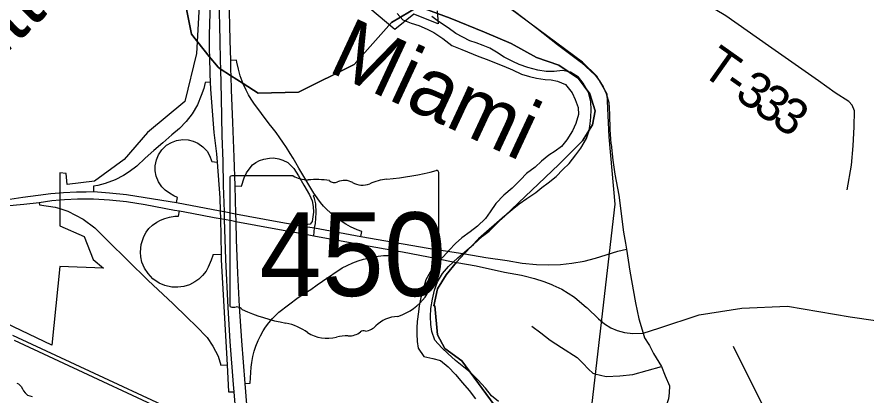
# Model space of a CAD drawing. Extents: x 44.2 to 78.2, y 4.5 to 26.5.
# Drawn here: x 50.4 to 51.74, y 20.558 to 21.155 of the extents above; entities that cross this region are included whole.
import ezdxf

# ---------------------------------------------------------------- set-up
doc = ezdxf.new("R2010")
doc.units = 0
for name, color, linetype in [('GM_X_Corporation', 7, 'Continuous'), ('GM_X_County_Road', 7, 'Continuous'), ('GM_X_Interchange_Ramps', 7, 'Continuous'), ('GM_X_Interstate_Route', 7, 'Continuous'), ('GM_X_Major_River', 7, 'Continuous'), ('GM_X_Major_River_Text', 7, 'Continuous'), ('GM_X_Minor_River', 7, 'Continuous'), ('GM_X_Rail_Line', 7, 'Continuous'), ('GM_X_State_Location', 7, 'Continuous'), ('GM_X_State_Route', 7, 'Continuous'), ('GM_X_State_Shield', 7, 'Continuous'), ('GM_X_Township_Road', 7, 'Continuous'), ('GM_X_Township_Road_Text', 7, 'Continuous'), ('GM_X_US_Route', 7, 'Continuous')]:
    doc.layers.add(name, color=color, linetype=linetype)

msp = doc.modelspace()

# ---------------------------------------------------------------- linework, layer by layer
at = {"layer": 'GM_X_Corporation'}
for points in [[(51.0623, 21.1648), (51.0641, 21.1438), (51.0258, 21.1593), (50.996, 21.1352), (50.8511, 21.2568)], [(50.6902, 21.2298), (50.6832, 21.0974), (50.6644, 21.0219), (50.6057, 20.9726), (50.5688, 20.9301), (50.5222, 20.8962), (50.4792, 20.891), (50.4777, 20.9083), (50.4673, 20.9092), (50.4673, 20.8259), (50.5059, 20.8087), (50.5198, 20.7725), (50.5363, 20.7591), (50.4673, 20.7615), (50.455, 20.6374), (50.3201, 20.7016)]]:
    msp.add_lwpolyline(points, dxfattribs=at)
at = {"layer": 'GM_X_County_Road'}
msp.add_lwpolyline([(50.3952, 20.6454), (50.7135, 20.4974)], dxfattribs=at)
at = {"layer": 'GM_X_Interchange_Ramps'}
for points in [[(50.7166, 21.2485), (50.7105, 21.2484), (50.7063, 21.2085), (50.7042, 21.1601), (50.7031, 21.1275), (50.7031, 21.1023), (50.7034, 21.0922), (50.7042, 21.0655), (50.7048, 21.0521)], [(50.7568, 21.0494), (50.755, 21.0538), (50.7521, 21.0623), (50.7491, 21.0728), (50.7464, 21.0837), (50.7459, 21.0866), (50.7364, 21.0864)], [(50.7048, 21.0521), (50.6967, 21.0518), (50.6943, 21.0422), (50.6906, 21.0309), (50.6848, 21.0165), (50.6762, 21.0022), (50.6666, 20.9902), (50.656, 20.9792), (50.644, 20.9689), (50.6299, 20.9566), (50.6156, 20.9446), (50.6022, 20.9323), (50.5888, 20.9199), (50.5768, 20.911), (50.5679, 20.9052), (50.5546, 20.8984), (50.5391, 20.8922), (50.5275, 20.8894), (50.5203, 20.8884), (50.5203, 20.8796)], [(50.7048, 21.0521), (50.7052, 21.0413), (50.7105, 20.973), (50.7147, 20.9394), (50.7157, 20.9263)], [(50.9422, 20.8088), (50.9435, 20.8168), (50.9364, 20.8193), (50.9261, 20.8243), (50.9184, 20.8284), (50.9111, 20.833), (50.9053, 20.8371), (50.8997, 20.8414), (50.8936, 20.8466), (50.8886, 20.8514), (50.8834, 20.8568), (50.8785, 20.8626), (50.8742, 20.8681), (50.8695, 20.875), (50.8682, 20.877), (50.8446, 20.9164), (50.8398, 20.9249), (50.8355, 20.9322), (50.8309, 20.9398), (50.825, 20.9489), (50.8191, 20.9577), (50.8146, 20.9643), (50.8085, 20.9727), (50.8023, 20.9809), (50.7978, 20.9867), (50.7736, 21.019), (50.7694, 21.0251), (50.765, 21.0324), (50.7612, 21.0396), (50.7568, 21.0494)], [(50.6515, 20.8623), (50.653, 20.8702), (50.6472, 20.8729), (50.6403, 20.8773), (50.6338, 20.882), (50.6284, 20.8873), (50.6233, 20.8949), (50.6196, 20.9039), (50.618, 20.9125), (50.618, 20.9205), (50.6199, 20.9299), (50.6232, 20.9378), (50.6284, 20.9455), (50.6359, 20.9526), (50.6435, 20.9572), (50.6514, 20.9601), (50.6613, 20.9617), (50.6697, 20.9612), (50.6775, 20.9594), (50.6851, 20.956), (50.6931, 20.9504), (50.6996, 20.9433), (50.7041, 20.9357), (50.7069, 20.9279), (50.7071, 20.9269), (50.7157, 20.9263)], [(50.7157, 20.9263), (50.72, 20.87), (50.7204, 20.8491), (50.7207, 20.8372), (50.7219, 20.7803)], [(50.7434, 20.8885), (50.7539, 20.8881), (50.758, 20.9015), (50.7619, 20.9093), (50.7675, 20.9173), (50.7714, 20.9217), (50.7766, 20.9256), (50.7823, 20.9286), (50.7894, 20.9308), (50.7983, 20.9325), (50.8042, 20.9329), (50.8126, 20.9312), (50.8189, 20.9292), (50.8269, 20.9256), (50.8317, 20.921), (50.8365, 20.9162), (50.8439, 20.9043), (50.8523, 20.89), (50.8614, 20.8748), (50.8655, 20.8651), (50.8668, 20.8562), (50.8673, 20.8471), (50.8666, 20.8399), (50.8655, 20.8328), (50.8621, 20.8284), (50.8548, 20.8271), (50.8545, 20.8249)], [(50.8679, 20.8102), (50.8693, 20.8223), (50.8705, 20.8294), (50.8718, 20.8463), (50.8713, 20.8603), (50.8691, 20.8687), (50.8675, 20.873), (50.8695, 20.875)], [(50.4348, 20.8627), (50.4355, 20.8589), (50.4602, 20.8549), (50.4673, 20.8528)], [(50.4673, 20.8528), (50.4803, 20.8489), (50.504, 20.8363), (50.5224, 20.8226), (50.5431, 20.8022), (50.5753, 20.7704), (50.6061, 20.7401), (50.6463, 20.7026), (50.6682, 20.6814), (50.6825, 20.6676), (50.6999, 20.6495), (50.7089, 20.6363), (50.7172, 20.6201), (50.7216, 20.606), (50.7313, 20.6065)], [(50.7219, 20.7803), (50.7087, 20.7799), (50.7085, 20.7789), (50.7062, 20.7716), (50.7015, 20.7604), (50.698, 20.7542), (50.6926, 20.7473), (50.6867, 20.7416), (50.6806, 20.7373), (50.6718, 20.7328), (50.663, 20.7301), (50.6537, 20.7288), (50.6441, 20.7292), (50.6333, 20.7316), (50.6242, 20.7355), (50.6142, 20.7423), (50.6065, 20.7504), (50.6009, 20.759), (50.597, 20.7684), (50.5951, 20.7767), (50.5945, 20.7844), (50.5956, 20.7963), (50.5997, 20.8088), (50.6034, 20.8155), (50.608, 20.8217), (50.6138, 20.827), (50.6203, 20.8316), (50.6262, 20.8348), (50.6329, 20.8375), (50.6402, 20.8395), (50.649, 20.8408), (50.6546, 20.8409), (50.6561, 20.8493)], [(50.7219, 20.7803), (50.7221, 20.7722), (50.7313, 20.6065), (50.7336, 20.564), (50.7418, 20.5642)], [(50.7593, 20.577), (50.7677, 20.5775), (50.7692, 20.6031), (50.77, 20.6102), (50.7717, 20.6198), (50.7738, 20.6282), (50.7764, 20.6361), (50.78, 20.645), (50.7837, 20.6526), (50.7881, 20.6603), (50.7918, 20.666), (50.797, 20.673), (50.8026, 20.6795), (50.8084, 20.6855), (50.8126, 20.6894), (50.8431, 20.7127), (50.8541, 20.7197), (50.8631, 20.7256), (50.8731, 20.7325), (50.8817, 20.7386), (50.9129, 20.7594), (50.9206, 20.7633), (50.9296, 20.7672), (50.9381, 20.7704), (50.9464, 20.773), (50.9536, 20.7749), (50.9609, 20.7764), (50.9696, 20.7779), (50.978, 20.7788), (50.9848, 20.7792), (50.9919, 20.7793), (50.9974, 20.7789), (50.9986, 20.7863)]]:
    msp.add_lwpolyline(points, dxfattribs=at)
at = {"layer": 'GM_X_Interstate_Route'}
for points in [[(50.7181, 21.1857), (50.7198, 21.1179), (50.7205, 21.0861), (50.7207, 21.0727), (50.7218, 21.0275), (50.7232, 20.9673), (50.7243, 20.9274), (50.7253, 20.8894), (50.7264, 20.8481), (50.7267, 20.8361), (50.7288, 20.7728), (50.7323, 20.6971), (50.7358, 20.6432), (50.7407, 20.5758), (50.7418, 20.5642), (50.7453, 20.5188)], [(50.7341, 21.186), (50.7357, 21.1182), (50.7364, 21.0864)], [(50.7364, 21.0864), (50.7368, 21.0715), (50.737, 21.0622), (50.7375, 21.0398), (50.7399, 20.9886), (50.742, 20.9341), (50.7434, 20.8885), (50.7445, 20.8446), (50.7448, 20.8328), (50.7456, 20.8038), (50.7478, 20.7513), (50.7503, 20.6987), (50.7539, 20.6447), (50.7593, 20.577), (50.7644, 20.5113)]]:
    msp.add_lwpolyline(points, dxfattribs=at)
at = {"layer": 'GM_X_Major_River'}
for points in [[(50.9993, 21.1602), (51.0082, 21.1505), (51.0218, 21.1453), (51.0335, 21.1413), (51.047, 21.1357), (51.0572, 21.1305), (51.0714, 21.1207), (51.0856, 21.1098), (51.1014, 21.1037), (51.1285, 21.0925), (51.1413, 21.0881), (51.1529, 21.0833), (51.1676, 21.0773), (51.1811, 21.0713), (51.1954, 21.0649), (51.2079, 21.0608), (51.2192, 21.0583), (51.2328, 21.0565), (51.2423, 21.0556), (51.2521, 21.0535), (51.2649, 21.0486), (51.2756, 21.0351), (51.28, 21.0248), (51.285, 21.0121), (51.2855, 21.0011), (51.2814, 20.9871), (51.2762, 20.9754), (51.2672, 20.9611), (51.2586, 20.9506), (51.2489, 20.9432), (51.2389, 20.937), (51.2273, 20.9277), (51.2169, 20.9184), (51.2034, 20.908), (51.194, 20.898), (51.1809, 20.8849), (51.1677, 20.8738), (51.1549, 20.8607), (51.1463, 20.848), (51.1388, 20.8375), (51.1264, 20.8252), (51.1148, 20.8163), (51.1017, 20.8067), (51.0916, 20.7981), (51.0815, 20.7873), (51.0726, 20.7776), (51.0621, 20.7679), (51.0515, 20.7526), (51.0448, 20.7405), (51.0407, 20.7254), (51.037, 20.7126), (51.0344, 20.6997), (51.0331, 20.6902), (51.0312, 20.675), (51.0303, 20.6648), (51.0304, 20.6553), (51.0309, 20.6435), (51.0326, 20.6331), (51.0414, 20.6197), (51.0558, 20.6167), (51.0679, 20.6134), (51.0798, 20.6033), (51.0913, 20.5916), (51.1024, 20.5785), (51.1131, 20.5661), (51.1231, 20.5533)], [(51.2857, 21.06), (51.2729, 21.0679), (51.2601, 21.0704), (51.2471, 21.0688), (51.2346, 21.069), (51.2214, 21.0708), (51.2055, 21.075), (51.192, 21.0798), (51.1818, 21.0846), (51.1683, 21.0917), (51.1559, 21.0992), (51.1454, 21.1055), (51.1349, 21.1099), (51.124, 21.1139), (51.1142, 21.1172), (51.1029, 21.1231), (51.092, 21.1287), (51.0797, 21.1377), (51.0644, 21.1479), (51.0543, 21.1557)], [(51.1595, 20.5491), (51.1483, 20.5577), (51.139, 20.5697), (51.1268, 20.5829), (51.1145, 20.5949), (51.1048, 20.6031), (51.0914, 20.6133), (51.0795, 20.6246), (51.0698, 20.6335), (51.0591, 20.6455), (51.0541, 20.6593), (51.0528, 20.67), (51.0519, 20.683), (51.0526, 20.6955), (51.0552, 20.7103), (51.0581, 20.7243), (51.063, 20.7375), (51.0712, 20.7506), (51.0806, 20.7615), (51.0949, 20.7753), (51.1061, 20.7845), (51.1201, 20.7964), (51.134, 20.8094), (51.1444, 20.8172), (51.1573, 20.8299), (51.1681, 20.8411), (51.1809, 20.8515), (51.1917, 20.8604), (51.204, 20.8689), (51.2179, 20.8785), (51.2276, 20.8859), (51.2376, 20.8933), (51.2504, 20.9037), (51.2608, 20.9145), (51.2705, 20.9238), (51.2811, 20.9376), (51.2889, 20.9481), (51.298, 20.9631), (51.302, 20.976), (51.3038, 20.9862), (51.3048, 20.9969), (51.3054, 21.0086), (51.3049, 21.0212), (51.3011, 21.0361), (51.2927, 21.0504), (51.2857, 21.06)]]:
    msp.add_lwpolyline(points, dxfattribs=at)
at = {"layer": 'GM_X_Minor_River'}
msp.add_lwpolyline([(50.3997, 20.578), (50.4023, 20.5768), (50.4064, 20.5725), (50.4086, 20.5686), (50.4104, 20.5656), (50.4126, 20.5625), (50.4167, 20.5589), (50.4201, 20.5577), (50.4238, 20.5569)], dxfattribs=at)
at = {"layer": 'GM_X_Rail_Line'}
for points in [[(51.7576, 19.9172), (51.6529, 19.9117), (51.5311, 19.911), (51.4655, 19.9391), (51.4402, 19.9542), (51.2895, 20.2613), (51.2813, 20.3233), (51.3434, 20.8596), (51.3339, 20.9662), (51.3307, 21.0331), (51.3143, 21.0616), (51.2918, 21.0838), (51.0931, 21.2312)], [(50.6639, 21.1832), (50.675, 21.1279), (50.7032, 21.0927), (50.7169, 21.0756), (50.7205, 21.0733), (50.7368, 21.0627), (50.7566, 21.0499), (50.7803, 21.0346), (50.844, 21.0365), (50.9317, 21.0802), (50.9905, 21.1461), (51.0331, 21.1714), (51.0833, 21.153), (51.1374, 21.1309), (51.1794, 21.1133), (51.2191, 21.0912), (51.2545, 21.079), (51.2854, 21.058), (51.3031, 21.0337), (51.3119, 21.0072), (51.3075, 20.9851), (51.292, 20.9597), (51.2545, 20.9222), (51.1694, 20.8415), (51.1275, 20.8051), (51.1057, 20.782), (51.0931, 20.7685), (51.0766, 20.7487), (51.0631, 20.7264), (51.0575, 20.6994), (51.0589, 20.6994), (51.0631, 20.6539), (51.0745, 20.6326), (51.1015, 20.6127), (51.2106, 20.4645)], [(51.2106, 20.4645), (51.1015, 20.6127), (51.0745, 20.6326), (51.0631, 20.6539), (51.0589, 20.6994), (51.0575, 20.6994), (51.0631, 20.7264), (51.0766, 20.7487), (51.0931, 20.7685), (51.1057, 20.782), (51.1275, 20.8051), (51.1694, 20.8415), (51.2545, 20.9222), (51.292, 20.9597), (51.3075, 20.9851), (51.3119, 21.0072), (51.3031, 21.0337), (51.2854, 21.058), (51.2545, 21.079), (51.2191, 21.0912), (51.1794, 21.1133), (51.1374, 21.1309), (51.0833, 21.153), (51.0331, 21.1714), (50.9905, 21.1461), (50.9317, 21.0802), (50.844, 21.0365), (50.7803, 21.0346), (50.7566, 21.0499), (50.7368, 21.0627), (50.7205, 21.0733), (50.7169, 21.0756), (50.7032, 21.0927), (50.675, 21.1279), (50.6639, 21.1832)], [(50.3927, 20.6536), (50.7634, 20.4811)]]:
    msp.add_lwpolyline(points, dxfattribs=at)
at = {"layer": 'GM_X_State_Route'}
msp.add_line((51.0624, 20.7741), (51.0897, 20.7687), dxfattribs=at)
for points in [[(50.3734, 20.8594), (50.3817, 20.8666), (50.4093, 20.8711), (50.4332, 20.8739), (50.4534, 20.8766), (50.4731, 20.8785), (50.4935, 20.8792), (50.5089, 20.8794), (50.5203, 20.8796)], [(50.5203, 20.8796), (50.5456, 20.8779), (50.5725, 20.875), (50.6021, 20.8704), (50.6515, 20.8623), (50.7204, 20.8491), (50.7264, 20.8481), (50.7445, 20.8446), (50.8104, 20.8326), (50.8545, 20.8249), (50.8693, 20.8223), (50.9422, 20.8088)], [(50.3734, 20.8594), (50.3824, 20.857), (50.4109, 20.8599), (50.4348, 20.8627), (50.455, 20.8654), (50.4682, 20.8667)], [(50.4682, 20.8667), (50.4747, 20.8673), (50.4951, 20.868), (50.5105, 20.8682), (50.5204, 20.8684), (50.5456, 20.8667), (50.5726, 20.8638), (50.6022, 20.8592), (50.6484, 20.8504), (50.6561, 20.8493), (50.6754, 20.8457)], [(50.6754, 20.8457), (50.7109, 20.839), (50.7138, 20.8385)], [(50.7138, 20.8385), (50.7207, 20.8372), (50.7267, 20.8361), (50.7385, 20.834), (50.7448, 20.8328), (50.8083, 20.8211), (50.8524, 20.8129), (50.8679, 20.8102), (50.94, 20.7967), (50.9481, 20.7953)], [(50.9422, 20.8088), (51.0481, 20.7906), (51.106, 20.7815), (51.1392, 20.7759), (51.173, 20.7709), (51.1968, 20.7671), (51.219, 20.7647), (51.2375, 20.7642), (51.2573, 20.7647), (51.2751, 20.7668), (51.2945, 20.7702), (51.312, 20.7745), (51.3476, 20.7859), (51.361, 20.789)], [(50.9481, 20.7953), (50.9986, 20.7863), (51.0077, 20.7845)], [(51.0077, 20.7845), (51.0487, 20.7767), (51.0624, 20.7741)], [(51.0897, 20.7687), (51.0933, 20.768), (51.1238, 20.7626), (51.1687, 20.7528), (51.1954, 20.7478), (51.1999, 20.7467)], [(51.1999, 20.7467), (51.2158, 20.7426), (51.2307, 20.7381), (51.2442, 20.7326)], [(51.2442, 20.7326), (51.2451, 20.7322), (51.2593, 20.726), (51.2793, 20.7134), (51.2983, 20.6969)], [(51.2983, 20.6969), (51.299, 20.6963), (51.3171, 20.6789), (51.3263, 20.6712), (51.3363, 20.6649), (51.3463, 20.6606), (51.3578, 20.6577), (51.371, 20.656), (51.3873, 20.6565)]]:
    msp.add_lwpolyline(points, dxfattribs=at)
at = {"layer": 'GM_X_State_Shield'}
for p, q in [((50.7355, 20.9011), (50.7355, 20.701)), ((50.8352, 20.9046), (50.7387, 20.9046)), ((51.0651, 20.8048), (51.0651, 20.9095)), ((51.065, 20.8049), (51.0651, 20.8048))]:
    msp.add_line(p, q, dxfattribs=at)
for centre, major_axis, start_param, end_param in [((50.9477, 21.1774), (0.3495, 0), 4.814394, 5.042369), ((51.0614, 20.91), (0.00367, 0), 6.141152, 7.989035), ((50.7392, 20.9016), (0.00382, 0), 1.712693, 3.28349), ((50.8582, 20.9278), (0.037, 0), 4.042523, 4.731795), ((50.8705, 20.7922), (0.133, 0), 1.404758, 1.657858), ((50.9922, 20.8435), (0.0703, 0), 1.699011, 2.107814), ((50.9007, 20.9026), (0.0107, 0), 3.836095, 5.185415), ((50.9164, 20.8795), (0.0222, 0), 0.950623, 2.079405), ((50.945, 20.9112), (0.0267, 0), 4.081561, 5.145723), ((51.0642, 20.7972), (0.00568, 0), 1.883978, 3.671073), ((51.0281, 20.7839), (0.0341, 0), 5.934695, 6.695948), ((51.0611, 20.8044), (0.00393, 0), 5.05454, 6.418171), ((51.0782, 20.761), (0.0248, 0), 2.387724, 3.262537), ((50.9672, 20.7477), (0.0874, 0), 5.101752, 6.440018), ((50.7393, 20.7006), (0.00385, 0), 3.00124, 4.508301), ((50.7399, 20.721), (0.0294, 0), 4.665946, 4.897461), ((50.7459, 20.6895), (0.0106, 0), 0.519207, 1.627899), ((50.8797, 20.8693), (0.2524, 0), 4.195997, 4.488961), ((50.8045, 20.6111), (0.079, 0), 0.823519, 1.323587), ((51.0041, 20.6448), (0.0479, 0), 1.647645, 2.488434), ((50.9225, 20.6735), (0.0267, 0), 4.691044, 5.507374), ((50.9466, 20.6541), (0.00752, 0), 1.147584, 2.315152), ((50.9434, 20.6816), (0.0282, 0), 4.937069, 5.64225), ((50.8899, 20.6885), (0.0501, 0), 4.026481, 4.996735), ((50.9188, 20.6193), (0.0412, 0), 1.495662, 1.94098)]:
    msp.add_ellipse(centre, major_axis=major_axis, ratio=0.8, start_param=start_param, end_param=end_param, dxfattribs=at)
at = {"layer": 'GM_X_Township_Road'}
for points in [[(51.7093, 20.8822), (51.7161, 20.9214), (51.7184, 20.9519), (51.7201, 20.9816), (51.7209, 21.0067), (51.717, 21.016), (51.7116, 21.0214), (51.6901, 21.0355), (51.6641, 21.0543), (51.5851, 21.1093), (51.5179, 21.1569), (51.4727, 21.1838), (51.4529, 21.1979), (51.4443, 21.2056), (51.4373, 21.2126), (51.4329, 21.2203), (51.4309, 21.2306), (51.4292, 21.2829), (51.4279, 21.3173)], [(51.3873, 20.6565), (51.4119, 20.6644), (51.4758, 20.6854), (51.543, 20.6961), (51.615, 20.6991), (51.7137, 20.6825), (51.7975, 20.67), (51.8403, 20.6676), (51.8718, 20.6605), (51.8938, 20.6581), (51.9259, 20.6535)], [(51.2117, 20.6676), (51.2261, 20.6572), (51.241, 20.6453), (51.2584, 20.6338), (51.2833, 20.6182), (51.2922, 20.6093), (51.3011, 20.6), (51.3078, 20.5934), (51.3113, 20.5926)], [(51.5971, 20.4958), (51.5956, 20.5035), (51.5301, 20.6354)], [(51.3113, 20.5926), (51.3289, 20.5885), (51.3505, 20.5893), (51.3709, 20.5914), (51.4165, 20.6041)]]:
    msp.add_lwpolyline(points, dxfattribs=at)
at = {"layer": 'GM_X_US_Route'}
for points in [[(51.0633, 21.2634), (51.0668, 21.2586), (51.0764, 21.2476), (51.0913, 21.2319), (51.1065, 21.2203), (51.1222, 21.2087), (51.1457, 21.192), (51.1864, 21.1625), (51.2197, 21.1372), (51.2523, 21.1114), (51.2901, 21.0832), (51.3116, 21.0632), (51.3186, 21.0543), (51.3242, 21.045), (51.3292, 21.0344), (51.3333, 21.02), (51.3343, 21.0015), (51.3346, 20.9768), (51.3366, 20.9553), (51.3367, 20.9543)], [(51.3367, 20.9543), (51.3397, 20.9291), (51.3429, 20.907), (51.3492, 20.8738), (51.3565, 20.8157), (51.3594, 20.7985)], [(51.3594, 20.7985), (51.361, 20.789), (51.3666, 20.7542), (51.3755, 20.7042), (51.3807, 20.679), (51.3873, 20.6565)], [(51.3873, 20.6565), (51.3894, 20.6494), (51.3962, 20.6388)], [(51.3962, 20.6388), (51.3972, 20.6372), (51.4035, 20.6245), (51.4165, 20.6041), (51.4221, 20.5893), (51.4288, 20.5737), (51.4284, 20.5625), (51.4273, 20.5529), (51.4232, 20.5407), (51.4165, 20.517)]]:
    msp.add_lwpolyline(points, dxfattribs=at)

# ---------------------------------------------------------------- texts
at = {"layer": 'GM_X_Major_River_Text'}
for s, rotation, p in [('Little', 44.0021, (50.3271, 21.043)), ('Miami', 334.9964, (50.888, 21.07))]:
    msp.add_text(s, height=0.0947, rotation=rotation, dxfattribs=at).set_placement(p)
at = {"layer": 'GM_X_State_Location'}
for s in ['s', 'r']:
    msp.add_text(s, height=0.000189, dxfattribs=at).set_placement((50.8966, 20.7878))
msp.add_text('450', height=0.000189, rotation=0, dxfattribs=at).set_placement((50.8297, 20.774))
at = {"layer": 'GM_X_State_Shield'}
msp.add_text('450', height=0.13184, dxfattribs=at).set_placement((50.7824, 20.7151))
at = {"layer": 'GM_X_Township_Road_Text'}
for s, rotation, p in [('T', 324.7408, (51.4761, 21.0665)), ('-', 324.74, (51.5108, 21.042)), ('3', 324.7746, (51.5299, 21.0285)), ('3', 324.8711, (51.5586, 21.0082)), ('3', 325.3318, (51.5876, 20.9878))]:
    msp.add_text(s, height=0.0568, rotation=rotation, dxfattribs=at).set_placement(p)

doc.saveas('drawing.dxf')
